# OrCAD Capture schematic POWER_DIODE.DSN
size A
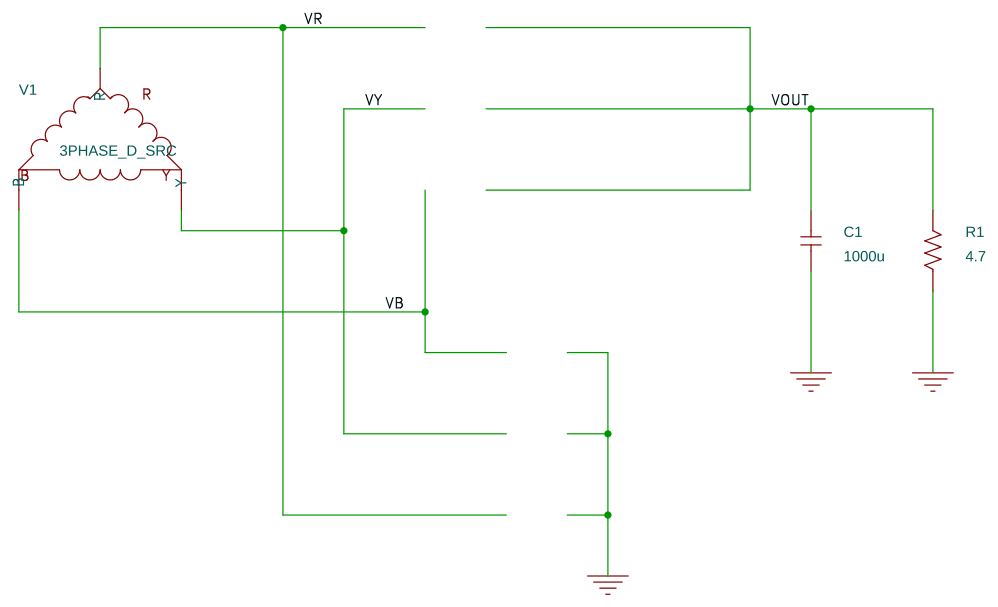
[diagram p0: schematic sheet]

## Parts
C1  1000u  [cap196]
R1  4.7  [AXRC05]
V1  3PHASE_D_SRC

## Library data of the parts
C1 = C
R1 = R
V1 = 3PHASE_D_SRC: AppProp: Three Phase$Voltage$0$-2; FREQ: 1k; L: 0; LV: 11; PH_B: 0240; PH_R: 0; PH_Y: 0120; R: 0; VPH: 1.1000e+1

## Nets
0: C1.1 R1.1
VB: V1.2(B)
VOUT: C1.2 R1.2
VR: V1.1(R)
VY: V1.3(Y)
